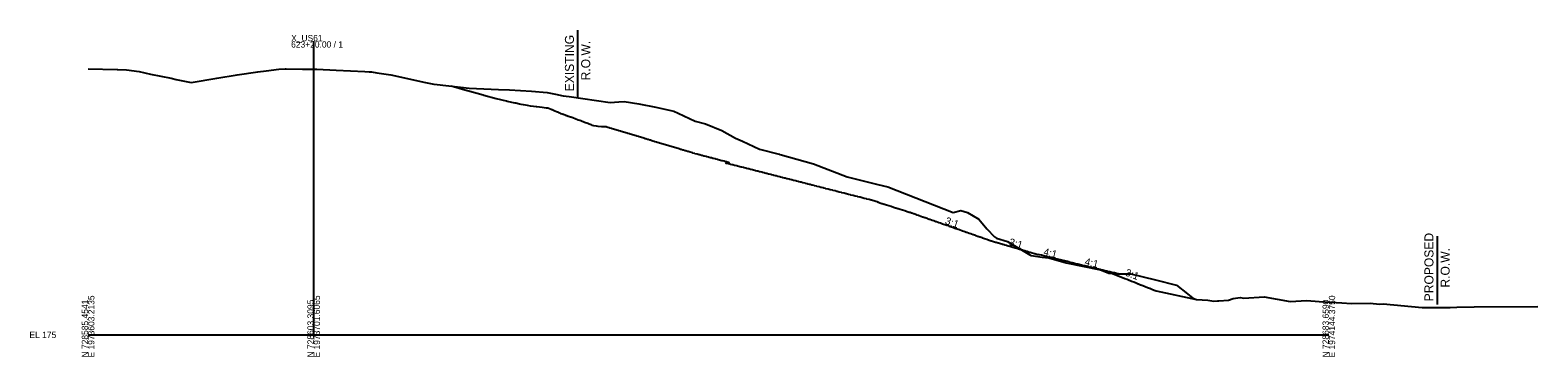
# Model space of a CAD drawing. Extents: x -26 to 1629, y -25 to 9635.
# Drawn here: x -26 to 643, y 7990 to 8135 of the extents above; entities that cross this region are included whole.
import ezdxf

# ---------------------------------------------------------------- set-up
doc = ezdxf.new("R2010")
doc.units = 0
for name, color, linetype in [('Draft_XS_Grid', 7, 'Continuous'), ('DTM_X_GROUND', 7, 'Continuous'), ('XS_CELL', 7, 'Continuous'), ('XS_P_GROUND', 7, 'Continuous'), ('XS_P_ROW', 7, 'Continuous'), ('XS_P_TX_FS_BS', 7, 'Continuous'), ('XS_X_ROW', 7, 'Continuous')]:
    doc.layers.add(name, color=color, linetype=linetype)

msp = doc.modelspace()

# ---------------------------------------------------------------- linework, layer by layer
at = {"layer": 'DTM_X_GROUND'}
msp.add_lwpolyline([(0, 8117.79), (12.81, 8117.54), (13.1, 8117.53), (13.18, 8117.53), (16.97, 8117.34), (22.62, 8116.66), (27.62, 8115.42), (36.78, 8113.65), (39.09, 8113.14), (45.68, 8111.69), (57.12, 8113.63), (66.02, 8115.1), (75.21, 8116.49), (78.92, 8116.94), (84.58, 8117.63), (87.36, 8117.79), (87.78, 8117.81), (95, 8117.69), (101.46, 8117.57), (109.9, 8117.19), (122.62, 8116.63), (124.56, 8116.5), (125.64, 8116.43), (128.02, 8116.06), (134.12, 8115.09), (149.62, 8111.78), (153.21, 8111), (154.76, 8110.86), (168.92, 8109.16), (181.98, 8108.64), (186.81, 8108.45), (196.49, 8107.95), (203.45, 8107.37), (207.12, 8106.6), (210.6, 8105.77), (213.21, 8105.6), (231.42, 8102.92), (235.27, 8103.14), (237.67, 8103.28), (244.18, 8102.33), (251.6, 8100.77), (259.57, 8099.1), (261.61, 8098.13), (269.06, 8094.57), (273.71, 8093.44), (280.97, 8090.54), (286.94, 8087.13), (290.05, 8085.77), (297.63, 8082.28), (306.39, 8080.05), (306.61, 8079.99), (306.79, 8079.94), (321.52, 8075.74), (336.54, 8069.99), (350.14, 8066.57), (354.48, 8065.51), (383.53, 8054.15), (386.93, 8055.09), (389.85, 8054.2), (394.84, 8051.25), (398.33, 8047.03), (401.76, 8043.49), (402.75, 8042.8), (407.59, 8041.32), (417.48, 8035.39), (418, 8035.12), (422.96, 8034.45), (425.81, 8034.18), (433.54, 8031.85), (448.74, 8028.74), (452.51, 8027.29), (455.48, 8027.02), (462.28, 8027), (473.18, 8024.38), (482.4, 8021.96), (487.38, 8018.13), (489.73, 8016.34), (491.29, 8015.66), (496.35, 8015.34), (499, 8014.92), (500.63, 8015.06), (501.19, 8015.08), (505.49, 8015.38), (507.61, 8016.16), (510.65, 8016.49), (512.34, 8016.27), (521.32, 8016.88), (532.82, 8014.74), (540.29, 8015.18), (545.71, 8014.72), (555.7, 8014.16), (560.1, 8013.86), (568.32, 8013.98), (572.39, 8013.56), (574.1, 8013.7), (591.39, 8012.13), (591.85, 8012.11), (603.8, 8012.16), (606.69, 8012.29), (614.36, 8012.44), (642.65, 8012.6)], dxfattribs=at)
at = {"layer": 'XS_CELL'}
for p, q in [((100, 8000), (100, 8130)), ((0, 8000), (100, 8000)), ((100, 8000), (550, 8000))]:
    msp.add_line(p, q, dxfattribs=at)
at = {"layer": 'XS_P_GROUND'}
msp.add_line((473.43, 8019.49), (491.29, 8015.66), dxfattribs=at)
msp.add_line((473.43, 8019.49), (491.29, 8015.66), dxfattribs=at)
for points in [[(214.88, 8096.05), (214.03, 8096.33), (213.85, 8096.39), (212.91, 8096.7), (212.82, 8096.73), (212.23, 8096.93), (212.22, 8096.93), (211.94, 8097.04), (211.79, 8097.11), (211.76, 8097.12), (210.76, 8097.52), (210.54, 8097.61), (209.73, 8097.94), (209.32, 8098.11), (208.7, 8098.36), (208.7, 8098.36), (208.7, 8098.36), (208.7, 8098.36), (208.7, 8098.36), (208.7, 8098.36), (208.7, 8098.36), (208.69, 8098.36), (208.69, 8098.36), (208.69, 8098.36), (208.69, 8098.36), (208.69, 8098.36), (208.69, 8098.36), (208.69, 8098.36), (208.69, 8098.36), (208.68, 8098.36), (208.68, 8098.36), (208.68, 8098.37), (208.67, 8098.37), (208.67, 8098.37), (208.67, 8098.37), (208.65, 8098.38), (208.63, 8098.38), (208.62, 8098.39), (208.61, 8098.39), (208.61, 8098.39), (208.61, 8098.39), (208.06, 8098.62), (207.66, 8098.78), (206.89, 8099.09), (206.63, 8099.19), (205.67, 8099.58), (205.6, 8099.61), (205.21, 8099.77), (204.57, 8100.03), (204.47, 8100.07), (203.72, 8100.37), (203.11, 8100.43), (201.33, 8100.6), (198.87, 8100.9), (198.79, 8100.91), (198.72, 8100.92), (196.05, 8101.32), (194.81, 8101.54), (193.03, 8101.85), (191.94, 8102.06), (191.2, 8102.21), (189.63, 8102.52), (189.35, 8102.59), (185.71, 8103.39), (185.44, 8103.46), (181.06, 8104.52), (180.82, 8104.58), (175.37, 8106), (175.18, 8106.06), (168.13, 8108.02), (168.01, 8108.05), (161, 8110.11)], [(350.43, 8058.69), (350.19, 8058.75), (350.16, 8058.76), (347.2, 8059.63), (347.1, 8059.66), (346.2, 8059.88), (346.09, 8059.91), (345.19, 8060.14), (345.08, 8060.17), (344.19, 8060.4), (344.07, 8060.43), (343.18, 8060.65), (343.06, 8060.68), (342.18, 8060.91), (342.05, 8060.94), (341.17, 8061.16), (341.04, 8061.2), (340.17, 8061.42), (340.03, 8061.45), (339.16, 8061.67), (339.02, 8061.71), (338.16, 8061.93), (338.01, 8061.97), (337.15, 8062.19), (337, 8062.23), (336.15, 8062.44), (335.99, 8062.48), (335.14, 8062.7), (334.98, 8062.74), (334.13, 8062.95), (333.97, 8063), (333.13, 8063.21), (332.96, 8063.25), (332.12, 8063.47), (331.95, 8063.51), (331.12, 8063.72), (330.94, 8063.77), (330.11, 8063.98), (329.93, 8064.02), (329.11, 8064.23), (328.92, 8064.28), (328.1, 8064.49), (327.91, 8064.54), (327.09, 8064.74), (326.9, 8064.79), (326.09, 8065), (325.89, 8065.05), (325.08, 8065.26), (324.88, 8065.31), (324.08, 8065.51), (323.87, 8065.57), (323.07, 8065.77), (322.86, 8065.82), (322.06, 8066.02), (321.85, 8066.08), (321.06, 8066.28), (320.84, 8066.34), (320.05, 8066.54), (319.83, 8066.59), (319.05, 8066.79), (318.82, 8066.85), (318.04, 8067.05), (317.81, 8067.11), (317.03, 8067.3), (316.8, 8067.36), (316.03, 8067.56), (315.79, 8067.62), (315.02, 8067.82), (314.78, 8067.88), (314.01, 8068.07), (313.77, 8068.14), (313.01, 8068.33), (312.76, 8068.39), (312, 8068.58), (311.75, 8068.65), (311, 8068.84), (310.74, 8068.91), (309.99, 8069.1), (309.73, 8069.16), (308.98, 8069.35), (308.72, 8069.42), (307.98, 8069.61), (307.7, 8069.68), (306.97, 8069.86), (306.69, 8069.93), (305.96, 8070.12), (305.68, 8070.19), (304.95, 8070.38), (304.67, 8070.45), (303.95, 8070.63), (303.66, 8070.71), (302.94, 8070.89), (302.65, 8070.96), (301.93, 8071.15), (301.64, 8071.22), (300.93, 8071.4), (300.63, 8071.48), (299.92, 8071.66), (299.62, 8071.73), (298.91, 8071.91), (298.61, 8071.99), (297.91, 8072.17), (297.6, 8072.25), (296.9, 8072.43), (296.59, 8072.5), (295.89, 8072.68), (295.58, 8072.76), (294.89, 8072.94), (294.57, 8073.02), (293.88, 8073.2), (293.56, 8073.28), (292.87, 8073.45), (292.55, 8073.53), (291.86, 8073.71), (291.54, 8073.79), (290.86, 8073.96), (290.53, 8074.05), (289.85, 8074.22), (289.52, 8074.3), (288.84, 8074.48), (288.51, 8074.56), (287.84, 8074.73), (287.5, 8074.82), (286.83, 8074.99), (286.49, 8075.07), (285.82, 8075.25), (285.48, 8075.33), (284.81, 8075.5), (284.47, 8075.59), (283.81, 8075.76), (283.46, 8075.85), (282.98, 8075.97), (282.7, 8076.04), (282.67, 8076.05), (283.77, 8076.03), (284.11, 8076.12), (283.94, 8076.33), (283.28, 8076.5), (282.94, 8076.59), (282.28, 8076.76), (281.94, 8076.85), (281.28, 8077.02), (280.94, 8077.11), (280.28, 8077.28), (279.94, 8077.37), (279.28, 8077.55), (278.94, 8077.63), (278.28, 8077.81), (277.94, 8077.9), (277.28, 8078.07), (276.94, 8078.16), (276.28, 8078.33), (275.94, 8078.42), (275.26, 8078.6), (274.94, 8078.68), (274.23, 8078.86), (273.94, 8078.94), (273.19, 8079.14), (272.94, 8079.2), (272.15, 8079.41), (271.94, 8079.46), (271.11, 8079.68), (270.94, 8079.72), (270.06, 8079.95), (269.94, 8079.98), (269, 8080.23), (268.94, 8080.24), (267.99, 8080.53), (267.94, 8080.54), (267.93, 8080.55), (266.94, 8080.84), (266.82, 8080.88), (265.94, 8081.15), (265.73, 8081.2), (264.94, 8081.45), (264.66, 8081.52), (263.94, 8081.75), (263.6, 8081.84), (262.94, 8082.05), (262.55, 8082.15), (261.94, 8082.35), (261.51, 8082.46), (260.94, 8082.65), (260.47, 8082.77), (259.94, 8082.95), (259.44, 8083.08), (258.94, 8083.25), (258.41, 8083.39), (257.94, 8083.55), (257.38, 8083.7), (256.94, 8083.85), (256.36, 8084.01), (255.94, 8084.16), (255.34, 8084.31), (254.94, 8084.46), (254.32, 8084.62), (253.94, 8084.76), (253.3, 8084.93), (252.94, 8085.06), (252.29, 8085.23), (251.94, 8085.36), (251.29, 8085.53), (250.94, 8085.67), (250.29, 8085.83), (249.94, 8085.97), (249.29, 8086.14), (248.94, 8086.27), (248.29, 8086.44), (247.94, 8086.57), (247.3, 8086.74), (246.94, 8086.87), (246.3, 8087.04), (245.94, 8087.18), (245.3, 8087.34), (244.94, 8087.48), (244.3, 8087.65), (243.94, 8087.78), (243.3, 8087.95), (242.94, 8088.08), (242.3, 8088.25), (241.94, 8088.39), (241.31, 8088.55), (240.94, 8088.69), (240.31, 8088.86), (239.94, 8088.99), (239.31, 8089.16), (238.94, 8089.3), (238.31, 8089.46), (237.94, 8089.6), (237.31, 8089.76), (236.94, 8089.9), (236.31, 8090.07), (235.94, 8090.21), (235.32, 8090.37), (234.94, 8090.51), (234.32, 8090.67), (233.94, 8090.81), (233.32, 8090.98), (232.94, 8091.12), (232.32, 8091.28), (231.94, 8091.42), (231.32, 8091.58), (230.94, 8091.72), (230.32, 8091.89), (229.94, 8092.03), (229.81, 8092.06), (229.72, 8092.09), (228.39, 8092.12), (227.96, 8092.12), (227.54, 8092.14), (226.17, 8092.2), (225.42, 8092.37), (224.16, 8092.58), (223.56, 8092.77), (223.13, 8092.95), (222.53, 8093.15), (222.1, 8093.34), (221.51, 8093.53), (221.06, 8093.72), (220.48, 8093.91), (220.03, 8094.1), (219.45, 8094.3), (219, 8094.49), (218.38, 8094.7), (217.97, 8094.88), (217.3, 8095.11), (216.94, 8095.27), (216.22, 8095.52), (215.91, 8095.66), (215.13, 8095.94), (214.88, 8096.05), (214.88, 8096.05), (214.88, 8096.05)], [(349.9, 8058.86), (349.97, 8058.84), (350.89, 8058.54), (350.97, 8058.52), (351.9, 8058.22), (351.98, 8058.2), (352.91, 8057.9), (352.98, 8057.88), (353.92, 8057.58), (353.98, 8057.56), (354.93, 8057.26), (354.99, 8057.24), (355.94, 8056.94), (355.99, 8056.93), (356.95, 8056.62), (357, 8056.61), (357.96, 8056.3), (358.01, 8056.29), (358.97, 8055.98), (359.02, 8055.97), (359.98, 8055.66), (360.02, 8055.65), (360.99, 8055.34), (361.03, 8055.33), (362, 8055.02), (362.04, 8055.01), (363.01, 8054.7), (363.05, 8054.69), (364.02, 8054.38), (364.04, 8054.37), (364.37, 8054.27), (365.01, 8054.04), (365.03, 8054.04), (365.18, 8053.98), (365.85, 8053.75), (366.04, 8053.68), (366.48, 8053.53), (366.9, 8053.38), (367.05, 8053.33), (367.38, 8053.21), (367.95, 8053.01), (368.06, 8052.97), (368.38, 8052.86), (369.07, 8052.62), (369.87, 8052.34), (370.08, 8052.27), (370.9, 8051.98), (371.09, 8051.91), (371.89, 8051.64), (372.1, 8051.56), (372.87, 8051.29), (373.11, 8051.21), (373.85, 8050.95), (374.12, 8050.85), (374.83, 8050.6), (375.13, 8050.5), (375.81, 8050.26), (376.14, 8050.15), (376.8, 8049.92), (377.15, 8049.79), (377.78, 8049.57), (378.16, 8049.44), (378.76, 8049.23), (379.17, 8049.08), (379.74, 8048.88), (380.18, 8048.73), (380.72, 8048.54), (381.19, 8048.38), (381.71, 8048.2), (382.2, 8048.02), (382.69, 8047.85), (383.21, 8047.67), (383.67, 8047.51), (384.22, 8047.32), (384.65, 8047.16), (385.23, 8046.96), (385.64, 8046.82), (386.24, 8046.61), (386.62, 8046.48), (387.25, 8046.25), (387.6, 8046.13), (388.26, 8045.9), (388.58, 8045.79), (389.27, 8045.55), (389.56, 8045.44), (390.28, 8045.19), (390.55, 8045.1), (391.29, 8044.84), (391.53, 8044.76), (392.3, 8044.49), (392.51, 8044.41), (393.31, 8044.13), (393.49, 8044.07), (394.32, 8043.78), (394.47, 8043.73), (395.33, 8043.43), (395.46, 8043.38), (396.34, 8043.07), (396.44, 8043.04), (397.35, 8042.72), (397.42, 8042.69), (398.36, 8042.36), (398.4, 8042.35), (399.37, 8042.01), (399.39, 8042.01), (399.87, 8041.84), (400.38, 8041.69), (400.41, 8041.68), (401.39, 8041.39), (402.29, 8041.13), (402.4, 8041.09), (402.53, 8041.06), (403.41, 8040.8), (403.59, 8040.74), (404.42, 8040.5), (405.09, 8040.3), (405.31, 8040.24), (405.34, 8040.23), (405.43, 8040.2), (406.14, 8039.99), (406.44, 8039.91), (407.04, 8039.73), (407.35, 8039.64), (407.39, 8039.63), (407.45, 8039.61), (407.83, 8039.5), (408.46, 8039.31), (409.04, 8039.14), (409.47, 8039.01), (409.95, 8038.87), (410.48, 8038.72), (411.01, 8038.56), (411.49, 8038.42), (412.07, 8038.25), (412.5, 8038.12), (412.89, 8038.01), (413.51, 8037.83), (414.19, 8037.63), (414.52, 8037.53), (415.25, 8037.32), (415.53, 8037.23), (416.31, 8037.01), (416.54, 8036.94), (417.37, 8036.69), (417.55, 8036.64), (418.43, 8036.38), (418.56, 8036.34), (419.49, 8036.07), (419.57, 8036.05), (419.65, 8036.03), (420.58, 8035.75), (421.17, 8035.58)], [(434.92, 8032.31), (434.88, 8032.32), (429.67, 8033.56), (428.88, 8033.75), (428.66, 8033.8), (427.84, 8033.99), (427.65, 8034.04), (426.8, 8034.24), (426.64, 8034.28), (425.76, 8034.49), (425.63, 8034.52), (424.72, 8034.73), (424.62, 8034.76), (423.68, 8034.98), (423.61, 8035), (422.64, 8035.23), (422.6, 8035.24), (421.61, 8035.47), (421.59, 8035.48), (421.17, 8035.58)], [(434.86, 8032.23), (434.92, 8032.31), (435.73, 8032.12), (436.16, 8032.02), (436.74, 8031.88), (437.2, 8031.77), (437.75, 8031.64), (438.24, 8031.52), (438.76, 8031.4), (439.28, 8031.28), (439.77, 8031.16), (440.32, 8031.03), (440.78, 8030.92), (441.36, 8030.78), (441.79, 8030.68), (442.4, 8030.54), (442.8, 8030.44), (443.44, 8030.29), (443.81, 8030.2), (444.48, 8030.04), (444.82, 8029.96), (445.52, 8029.8), (445.83, 8029.72), (446.56, 8029.55), (446.84, 8029.48), (447.6, 8029.3), (447.85, 8029.24), (448.64, 8029.05), (448.86, 8029), (449.68, 8028.81), (449.87, 8028.76), (450.72, 8028.56), (450.88, 8028.52), (451.76, 8028.31), (451.89, 8028.28), (452.79, 8028.07), (452.91, 8028.04), (453.83, 8027.82), (453.92, 8027.8), (454.87, 8027.57), (454.93, 8027.56), (455.91, 8027.33), (455.94, 8027.32), (456.67, 8027.15), (457.03, 8027.02)], [(453.46, 8027.48), (454.43, 8027.09), (458.58, 8025.43), (459.55, 8025.04), (459.58, 8025.03), (460.55, 8024.64), (460.58, 8024.63), (461.55, 8024.24), (461.59, 8024.23), (462.55, 8023.84), (462.59, 8023.83), (463.55, 8023.44), (463.59, 8023.43), (464.55, 8023.04), (464.59, 8023.03), (465.55, 8022.64), (465.59, 8022.63), (466.55, 8022.24), (466.59, 8022.23), (467.55, 8021.84), (467.59, 8021.83), (468.55, 8021.44), (468.59, 8021.43), (469.55, 8021.04), (469.59, 8021.03), (470.55, 8020.64), (470.59, 8020.63), (471.55, 8020.24), (471.59, 8020.23), (472.55, 8019.84), (472.58, 8019.83), (473.43, 8019.49)], [(453.46, 8027.48), (454.43, 8027.09), (458.58, 8025.43), (459.55, 8025.04), (459.58, 8025.03), (460.55, 8024.64), (460.58, 8024.63), (461.55, 8024.24), (461.59, 8024.23), (462.55, 8023.84), (462.59, 8023.83), (463.55, 8023.44), (463.59, 8023.43), (464.55, 8023.04), (464.59, 8023.03), (465.55, 8022.64), (465.59, 8022.63), (466.55, 8022.24), (466.59, 8022.23), (467.55, 8021.84), (467.59, 8021.83), (468.55, 8021.44), (468.59, 8021.43), (469.55, 8021.04), (469.59, 8021.03), (470.55, 8020.64), (470.59, 8020.63), (471.55, 8020.24), (471.59, 8020.23), (472.55, 8019.84), (472.58, 8019.83), (473.43, 8019.49)]]:
    msp.add_lwpolyline(points, dxfattribs=at)
at = {"layer": 'XS_P_ROW'}
msp.add_line((598, 8043.78), (598, 8013.46), dxfattribs=at)
at = {"layer": 'XS_X_ROW'}
msp.add_line((217, 8134.9), (217, 8105), dxfattribs=at)

# ---------------------------------------------------------------- texts
at = {"layer": 'Draft_XS_Grid'}
msp.add_text('-', height=0.0001, dxfattribs=at).set_placement((0, 8000))
at = {"layer": 'XS_CELL'}
for s, p in [('X_US61', (90, 8130)), ('623+20.00 / 1', (90, 8127.2)), ('EL 175', (-26, 7998.6))]:
    msp.add_text(s, height=2.8, dxfattribs=at).set_placement(p)
for s, p in [('N 728585.4541', (0, 7990)), ('E 1973603.2135', (2.8, 7990)), ('N 728603.3095', (100, 7990)), ('E 1973701.6065', (102.8, 7990)), ('N 728683.6590', (550, 7990)), ('E 1974144.3750', (552.8, 7990))]:
    msp.add_text(s, height=2.8, rotation=90, dxfattribs=at).set_placement(p)
at = {"layer": 'XS_P_ROW'}
for s, p in [('PROPOSED', (596.37, 8014.87)), ('R.O.W.', (603.57, 8020.94))]:
    msp.add_text(s, height=4, rotation=90, dxfattribs=at).set_placement(p)
at = {"layer": 'XS_P_TX_FS_BS'}
for s, rotation, p in [('3:1', 340.70169, (379.62, 8049.25)), ('3:1', 343.62595, (407.96, 8039.77)), ('4:1', 346.64053, (423.25, 8035.39)), ('4:1', 346.64053, (441.56, 8031.04)), ('3:1', 338.88387, (459.43, 8026.4))]:
    msp.add_text(s, height=3.24, rotation=rotation, dxfattribs=at).set_placement(p)
at = {"layer": 'XS_X_ROW'}
for s, p in [('EXISTING', (215.37, 8107.84)), ('R.O.W.', (222.57, 8112.68))]:
    msp.add_text(s, height=4, rotation=90, dxfattribs=at).set_placement(p)

doc.saveas('drawing.dxf')
